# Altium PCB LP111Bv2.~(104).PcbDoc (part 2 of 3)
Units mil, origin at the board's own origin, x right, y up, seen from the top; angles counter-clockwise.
Board outline 3543.31 x 7480.32 mil, 4 copper layers (Top Layer, Signal Layer 1, Signal Layer 2, Bottom Layer), stack 40 mil thick; 284 components, 118 nets, 594 pads, 103 vias.
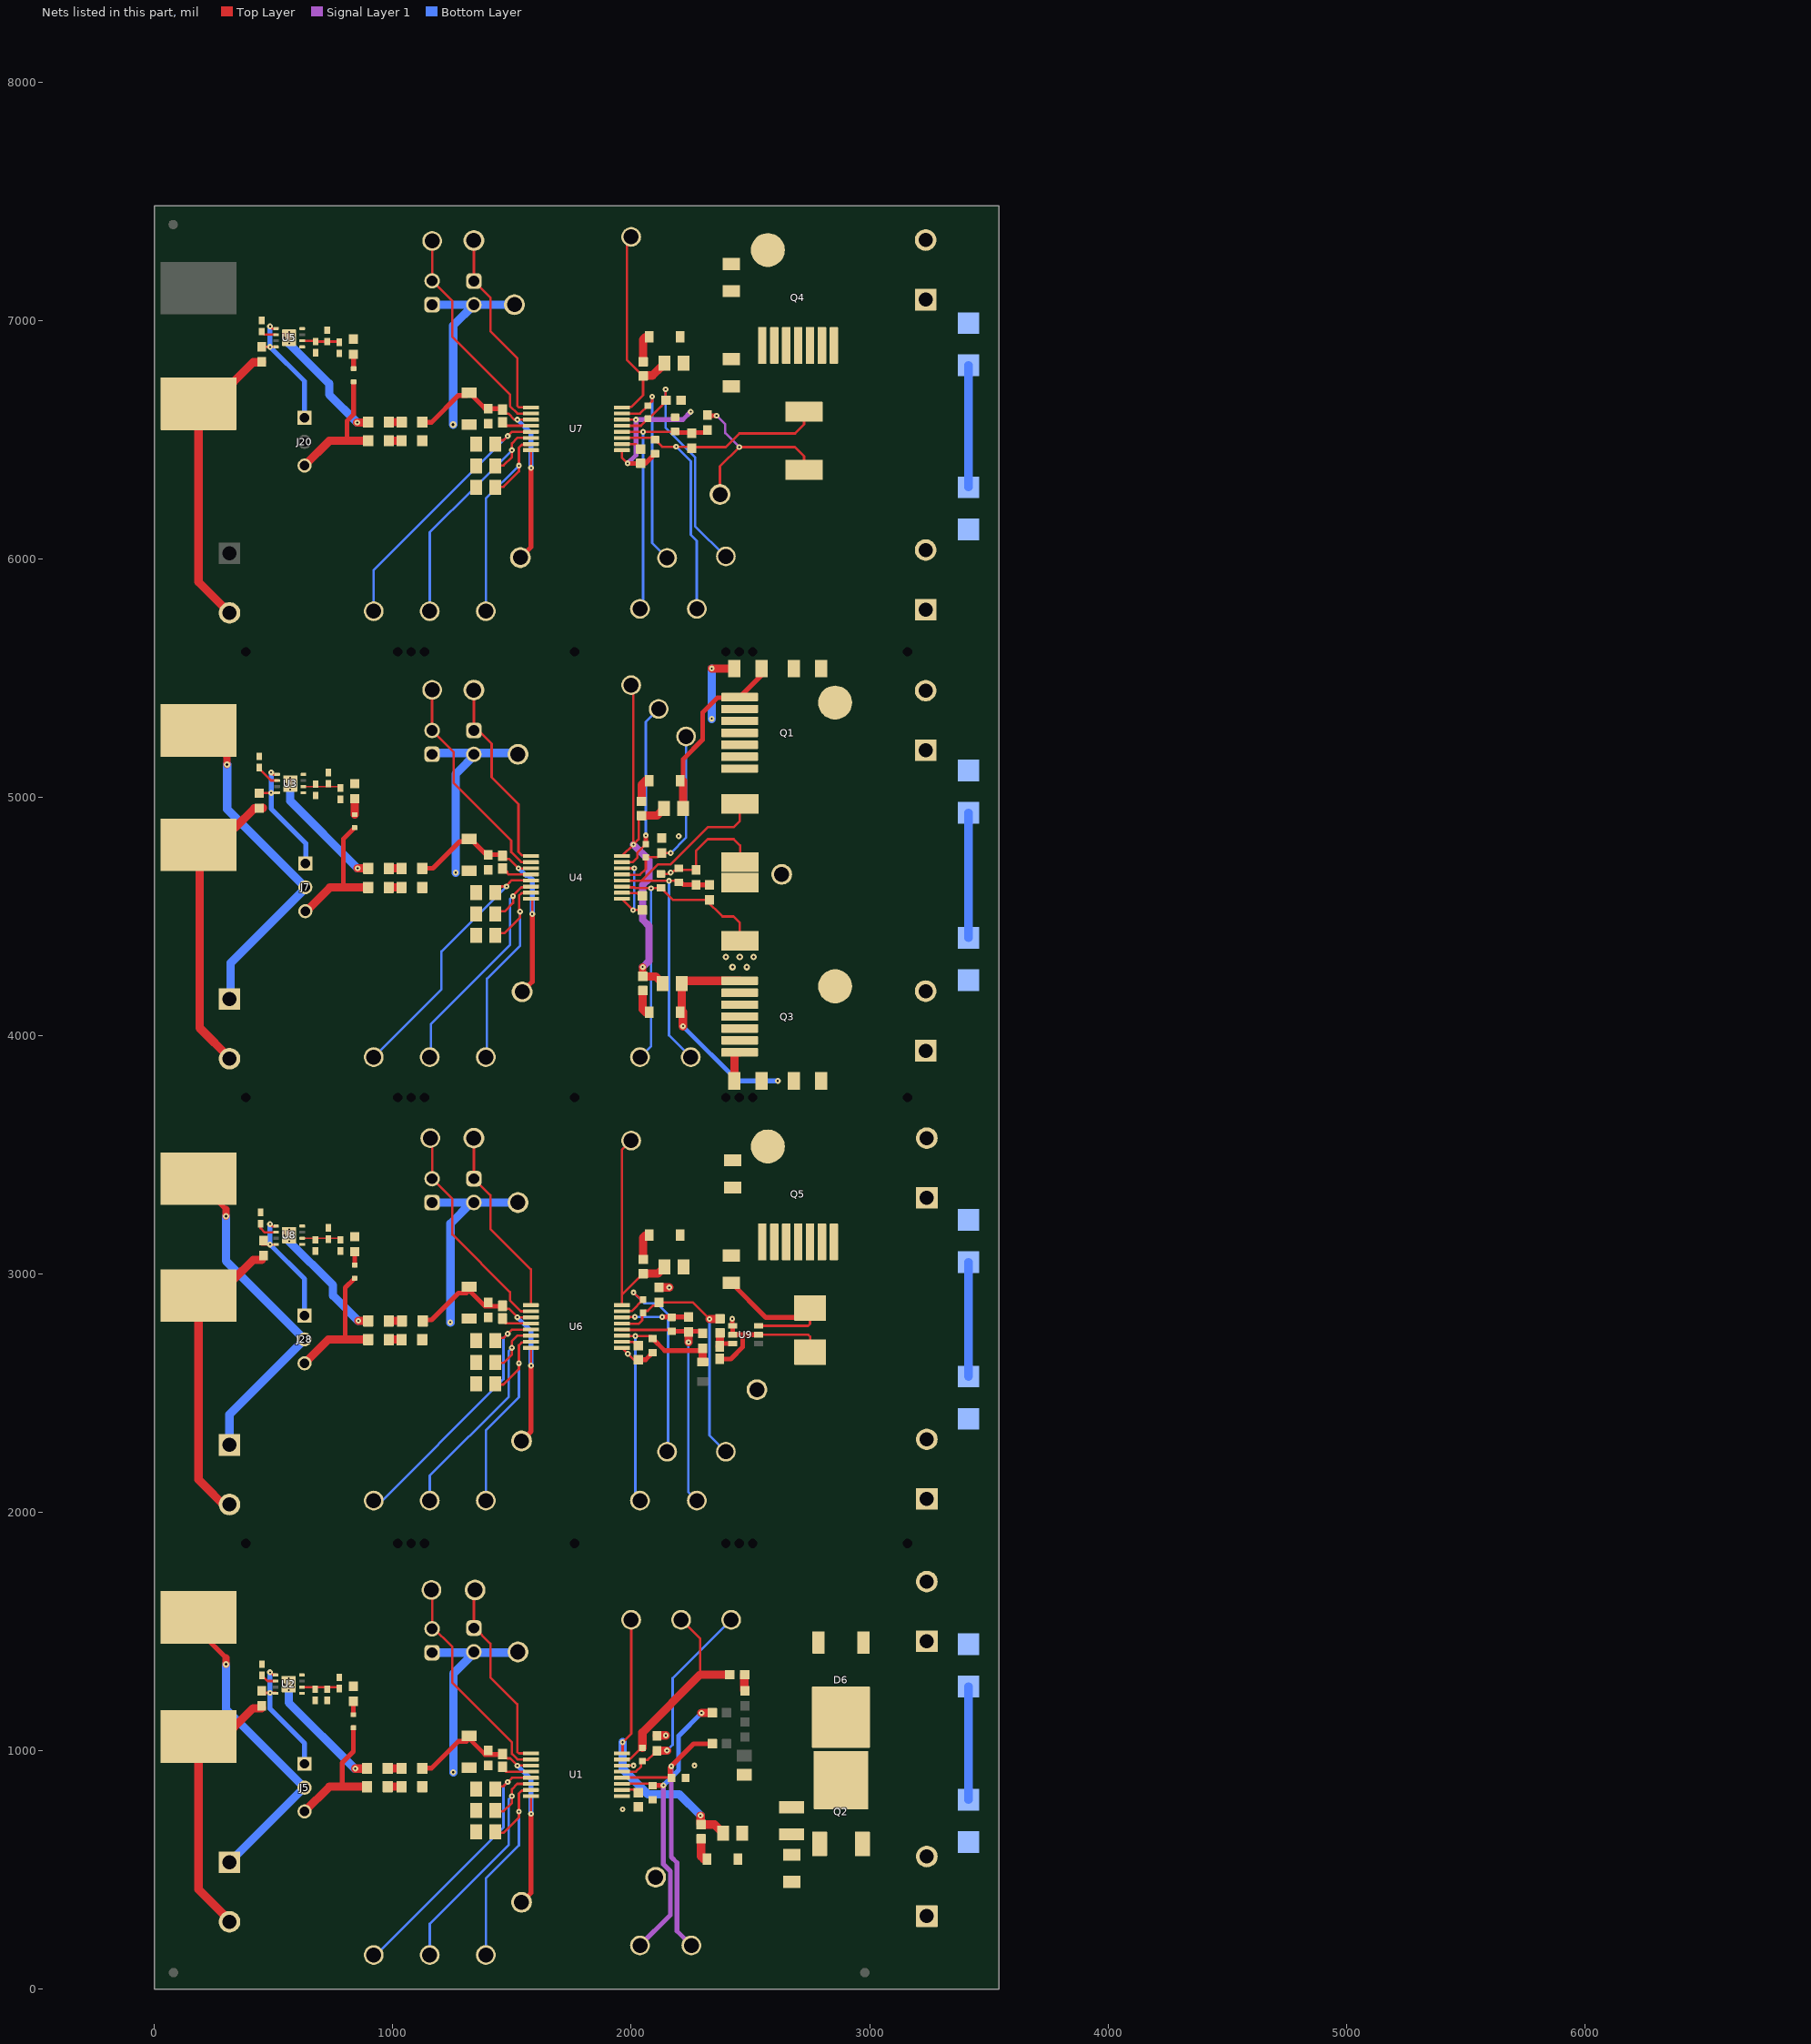
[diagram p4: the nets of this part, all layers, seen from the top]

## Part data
C1 C16 C33 C42: library part CMP-0081062-1, "CAP, CERM, 10 µF, 25 V,+/- 5%, X7R, AEC-Q200 Grade 1, 1206", Cap_Case=1206_180, Manufacturer=Kemet, Supplier Part Number 1=399-15734-1-ND, TempCo=X7R, Tolerance_%=5%, Value2=25V, ValueDisplayed=10µF
C2 C9 C19 C24 C34 C39 C43 C49: library part CMP-0007139-4, "CAP, CERM, 1 uF, 25 V, +/- 10%, X7R, AEC-Q200 Grade 1, 0603", Cap_Case=0603, Manufacturer=MuRata, Supplier Part Number 1=490-10673-1-ND, TempCo=X7R, Tolerance_%=10%, Value1=Unknown, Value2=25V, ValueDisplayed=1uF
C3 C5 C12 C15 C29 C31 C45 C52: library part CMP-0007501-1, "CAP, CERM, 10 uF, 25 V, +/- 20%, X5R, 0603", Cap_Case=0603, Manufacturer=MuRata, Supplier Part Number 1=490-12323-1-ND, TempCo=X5R, Tolerance_%=20%, Value1=Unknown, Value2=25V, ValueDisplayed=10uF
C4 C20 C35 C44 C53: library part CMP-0087061-2, "CAP CER 0.1UF 50V X7R 0603", Manufacturer=Kemet, TempCo=15%, Tolerance_%=10%
C6 C22 C37 C46: library part CMP-0030960-1, "Cap Ceramic 330nF 25V X7R 10% Pad SMD 0603 +125°C Automotive T/R", Manufacturer=TDK, Operating Temperature Range="-55°C to +125°C", TempCo=0.15, Temperature Characteristic=X7R, Tolerance_%=0.1%, ValueDisplayed=330nF
C7 C11 C13 C14 C30 C32 C47 C51: library part CMP-0006658-2, "CAP, CERM, 0.01 uF, 25 V, +/- 10%, X7R, 0402", Cap_Case=0402, Manufacturer=MuRata, Supplier Part Number 1=490-1312-1-ND, TempCo=X7R, Tolerance_%=10%, Value1=Unknown, Value2=25V, ValueDisplayed=0.01uF
C8 C10 C25 C26 C40 C41 C48 C50: library part CMP-0094870-1, "1000 pF ±10% 16V Ceramic Capacitor X7R 0603 (1608 Metric)", Digikey Part Number=311-4063-1-ND, Manufacturer=YAGEO, Mouser Part Number=603-CC603KRX7R7BB102, Operating Temperature Range="-55°C to +125°C", TempCo=15%, Temperature Characteristic=X7R, Tolerance_%=10%, ValueDisplayed="1.0 nF", Voltage=16V
C17: library part CMP-0009248-2, "CAP, CERM, 0.022 uF, 630 V, +/- 10%, X7R, 1210", Cap_Case=1210, Manufacturer=MuRata, Supplier Part Number 1=490-3514-1-ND, TempCo=X7R, Tolerance_%=10%, Value1=Unknown, Value2=630V, ValueDisplayed=0.022uF
C18 C23 C27 C38 C55: library part CMP-0008897-2, "CAP, CERM, 100 pF, 1000 V, +/- 5%, U2J, 1206", Cap_Case=1206, Manufacturer=MuRata, Supplier Part Number 1=490-4301-1-ND, TempCo=U2J, Tolerance_%=5%, Value1=Unknown, Value2=1000V, ValueDisplayed=100pF
C21 C28 C36 C54: library part CMP-0008902-2, "CAP, CERM, 68 pF, 1000 V, +/- 5%, U2J, 1206", Cap_Case=1206, Manufacturer=MuRata, Supplier Part Number 1=490-4300-1-ND, TempCo=U2J, Tolerance_%=5%, Value1=Unknown, Value2=1000V, ValueDisplayed=68pF
D1 D2 D3 D4 D11: library part CMP-0028526-2, "Diode, Schottky, 40 V, 0.5 A, SOD-123", Manufacturer="ON Semiconductor", Value1=0.5A, Value2=0.51V
D5 D8 D9 D12: library part CMP-0087203-1, "DIODE SCHOTTKY 60V 200MA SOD523", Manufacturer=Nexperia
D6: library part CMP-0092653-1, "Diode Silicon Carbide Schottky 600 V 11A (DC) Surface Mount TO-252-2", Digikey Part Number=C3D03060E-ND, Forward Current=11A, Manufacturer=Cree, Max Surge Forward Current=26A, Mouser Part Number=941-C3D03060E, Operating Temperature Range="-55°C to +175°C", Peak Reverse Current=4uA, ValueDisplayed=166pF
D7 D10 D13 D14 D17 D18: library part CMP-03913-133963852-1, "824520402 Tvs Diode, Unidir, 400V, Smb Rohs Compliant: Yes", Leakage Current=1µA, Max Operating Temperature=150°C, Min Operating Temperature=-65°C
D15 D16: library part CMP-03913-133963857-1, "824521402 Tvs Diode, Bidir, 400V, Do-214Aa Rohs Compliant: Yes", Leakage Current=1µA, Max Operating Temperature=150°C, Min Operating Temperature=-65°C
FB1 FB2 FB3 FB4 FB5 FB6 FB7 FB8 FB9 FB10 FB11 FB12 FB13 FB14 FB15 FB16: library part CMP-0124406-1, "2.5 kOhms @ 100 MHz 1 Signal Line Ferrite Bead 0805 (2012 Metric) 200mA 700mOhm", Digikey Part Number=553-BBBK00201209252Y00CT-ND, Impedance At Frequency="2500Ω @ 100MHz", Manufacturer="Pulse Electronics", Mouser Part Number=673-BBBK201209252Y00, Operating Temperature Range="-55°C to +125°C", Tolerance_%=25%
FID1 FID2 FID3: library part CMP-0077181-1, "Fiducial mark.  There is nothing to buy or mount.", Manufacturer=N/A
H1 H2 H3 H4 H5 H6 H7 H8 H9 H10 H11 H12 H13 H14 H15 H16: library part CMP-0003620-1, "Bumpon, Hemisphere, 0.44 X 0.20, Clear", Manufacturer=3M, Supplier Part Number 1=SJ5303-7-ND
J1 J4 J15 J19: library part CMP-0079575-1, "Banana Jack Insul Nylon Red, TH", Color=Red, Current_A=15A, Manufacturer="Cinch Connectivity", Supplier Part Number 1=J151-ND
J2 J10 J17 J21: library part CMP-0079574-1, "Banana Jack Insul Nylon Black, TH", Color=Black, Current_A=15A, Manufacturer="Cinch Connectivity", Supplier Part Number 1=J152-ND
J3 J9 J11 J12 J13 J18 J22 J23 J24 J27 J31 J32: library part CMP-0093233-2, Current_A=32A, Digikey Part Number=732-691250610002-ND, Manufacturer="Wurth Electronics", Mouser Part Number=710-691250610002, Operating Temperature Range="-32°C to +120°C", Voltage_V=450V
J5 J7 J20 J28: library part CMP-0002338-1, "Header, 100mil, 3x1, Tin, TH", Color=Black, Current_A=3A, Manufacturer="Sullins Connector Solutions", Supplier Part Number 1=S1012E-03-ND, Voltage_V=1.8kV
J6 J8 J14 J16 J25 J26 J29 J30: library part CMP-0054794-2, "Header, 2.54 mm, 2x1, Gold, TH", Color=Black, Manufacturer="Wurth Elektronik", Supplier Part Number 1=732-5315-ND
Logo1: library part CMP-0074844-1
Logo2: library part CMP-0074838-1, "Texas Instrument Corporate Signature"
Logo3: library part CMP-0074847-1, "FCC_disclaimer"
Logo4: library part CMP-0074769-1
LOGO5 LOGO6 LOGO7 LOGO8: library part CMP-0074835-1, "IEC 61010-1 High Voltage Warning"
LOGO9: library part CMP-0074837-2, "IEC 61010-1 Hot Surface Warning", Manufacturer="Texas Instruments"
LOGO10: library part CMP-0074836-1, "IEC 61010-1 Caution Warning"
Q1 Q3 Q4 Q5: library part CMP-0120465-1, "MOSFET N-Channel 750 V 44A (Tc) 197W (Tc) Surface Mount D2PAK-7", Digikey Part Number=2312-UJ4C075033B7SCT-ND, Drain To Source Breakdown Voltage=750V, Input Capacitace At Vds="1400pF @ 400V", Manufacturer=Qorvo, Mouser Part Number=431-UJ4C075033B7S, Operating Temperature Range="-55°C to +175°C", Power_W=197W, Pulse Drain Current=140A, Typ Forward Diode Voltage=1.26V
Q2: library part CMP-0000528-4, "Transistor, IGBT, 600 V, 20 A, DPAK", Manufacturer=STMicroelectronics, Value1="20 A"
R1 R2 R3 R22 R23 R24 R34 R35 R36 R38 R39 R40: library part CMP-0020622-3, "RES, 100 k, 5%, 0.125 W, AEC-Q200 Grade 0, 0805", Manufacturer=Panasonic, Power_W=125mW, Supplier Part Number 1=P100KACT-ND, TempCo="200 ppm/C", Tolerance_%=5%, Value2=0.125W, Value_Code=100k
R4 R7 R13 R14 R16 R17 R21 R27 R30 R37 R46 R51: library part CMP-0031931-1, "0 Ohms Jumper Chip Resistor 0603 (1608 Metric) Metal Element", Digikey Part Number=541-3927-1-ND, Manufacturer=Vishay, Mouser Part Number=71-WSL060300000ZEA9, Operating Temperature Range="-65°C to +170°C", TempCo=3900ppm/°C
R5 R6 R10 R31 R48: library part CMP-0020848-3, "RES, 10.2, 1%, 0.125 W, AEC-Q200 Grade 0, 0805", Manufacturer=Vishay-Dale, Power_W=125mW, Supplier Part Number 1=541-10.2CCT-ND, TempCo="100 ppm/C", Tolerance_%=1%, Value2=0.125W, Value_Code=10R2, ValueDisplayed=10.2
R8 R11 R32 R49: library part CMP-0026693-1, "RES, 294 k, 1%, 0.1 W, AEC-Q200 Grade 0, 0402", Manufacturer=Panasonic, Power_W=100mW, Supplier Part Number 1=P294KLCT-ND, TempCo="100 ppm/C", Tolerance_%=1%, Value2=0.1W, Value_Code=294k
R9 R12 R33 R50: library part CMP-0026711-1, "RES, 90.9 k, 1%, 0.1 W, AEC-Q200 Grade 0, 0402", Manufacturer=Panasonic, Power_W=100mW, Supplier Part Number 1=P90.9KLCT-ND, TempCo="100 ppm/C", Tolerance_%=1%, Value2=0.1W, Value_Code=90k9, ValueDisplayed=90.9k
R15: library part CMP-0022494-4, "RES, 54.9 k, 1%, 0.1 W, AEC-Q200 Grade 0, 0603", Manufacturer=Vishay-Dale, Power_W=100mW, Supplier Part Number 1=541-54.9KHCT-ND, TempCo="100 ppm/C", Tolerance_%=1%, Value2=0.1W, Value_Code=54k9, ValueDisplayed=54.9k
R18: library part CMP-0022205-4, "RES, 20.5 k, 1%, 0.1 W, AEC-Q200 Grade 0, 0603", Manufacturer=Vishay-Dale, Power_W=100mW, Supplier Part Number 1=541-20.5KHCT-ND, TempCo="100 ppm/C", Tolerance_%=1%, Value2=0.1W, Value_Code=20k5, ValueDisplayed=20.5k
R19: library part CMP-0080491-1, "RES, 3.40 k, 1%, 0.1 W, 0603", Manufacturer="TT Electronics/IRC", Power_W=100mW, TempCo="100 ppm/C", Tolerance_%=1%, Value2=0.1W, Value_Code=3k40, ValueDisplayed=3.40k
R20: library part CMP-0021540-3, "RES, 11.5 k, 1%, 0.125 W, AEC-Q200 Grade 0, 0805", Manufacturer=Panasonic, Power_W=125mW, Supplier Part Number 1=P11.5KCCT-ND, TempCo="100 ppm/C", Tolerance_%=1%, Value2=0.125W, Value_Code=11k5, ValueDisplayed=11.5k
R25 R29 R41 R42 R44 R45: library part CMP-0025909-5, "RES, 2.0 k, 5%, 0.1 W, 0603", Manufacturer=Yageo, Power_W=100mW, Supplier Part Number 1=311-2.0KGRCT-ND, TempCo="100 ppm/C", Tolerance_%=5%, Value2=0.1W, Value_Code=2k00, ValueDisplayed=2.0k
R26 R28 R43: library part CMP-0123876-1, "Res Metal Strip 2512 0.06 Ohm 1% 3W ±50ppm/°C Pad SMD Automotive T/R", Digikey Part Number=118-CRA2512-FZ-R060ELFCT-ND, Manufacturer=Bourns, Mouser Part Number=652-CRA2512FZR060ELF, Operating Temperature Range="-55°C to +170°C", Power_W=3W, TempCo=50ppm/°C, Tolerance_%=1%
R47: library part CMP-0092692-1, "RES SMD 0 OHM JUMPER 1/8W 0805", Digikey Part Number=311-0.0CRCT-ND, Manufacturer=Yageo, Mouser Part Number=603-RC0805FR-070RL, Operating Temperature Range="-55°C to +155°C", Power_W=125mW, Tolerance_%=1%
R52: library part CMP-0120455-1, "Res Metal Plate 2512 0.003 Ohm 1% 3W ±75ppm/C Pad SMD Automotive T/R", Digikey Part Number=P17091CT-ND, Manufacturer=Panasonic, Mouser Part Number=667-ERJ-MS4SF3M0U, Operating Temperature Range="-65°C to +170°C", Power_W=3W, TempCo=75ppm/°C, Tolerance_%=1%
SH-J1 SH-J2 SH-J3 SH-J4 SH-J5 SH-J6 SH-J7 SH-J8 SH-J9 SH-J10 SH-J11 SH-J12: library part CMP-0003623-3, "Shunt, 100mil, Gold plated, Black", Alternate Manufacturer=3M, Alternate PartNumber=969102-0000-DA, Manufacturer=Samtec, Supplier Part Number 1=SAM8858-ND
TP1 TP3 TP4 TP7 TP9 TP10 TP11 TP12 TP13 TP15 TP16 TP17 TP18 TP20 TP21 TP22 TP23 TP24 TP27 TP29 TP31 TP32 TP33 TP34 TP35 TP36 TP37 TP38 TP42 TP43 TP46 TP47 TP48 TP49 TP50 TP51: library part CMP-1672-00004-4, "Test Point, White, Through Hole, RoHS, Bulk", Colour=White, Manufacturer=Keystone, Package Quantity=100
TP2 TP8 TP28 TP41: library part CMP-0055151-2, "Test Point, Multipurpose, Yellow, TH", Color=Yellow, Manufacturer="Keystone Electronics", PartNumber=5014, Supplier Part Number 1=36-5014-ND
TP5 TP14 TP30 TP44: library part CMP-0055147-2, "Test Point, Multipurpose, Red, TH", Color=Red, Manufacturer="Keystone Electronics", PartNumber=5010, Supplier Part Number 1=36-5010-ND
TP6 TP19 TP25 TP26 TP39 TP40 TP45 TP52: library part CMP-0055148-2, "Test Point, Multipurpose, Black, TH", Color=Black, Manufacturer="Keystone Electronics", Supplier Part Number 1=36-5011-ND
U1: library part CMP-0123884-1, Manufacturer="Texas Instruments", Operating Temperature Range=to
U2 U3 U5 U8: library part CMP-0073868-3, "Vin 3V to 36V, 150mA, Ultra-Low-Noise, High-PSRR Low-Dropout (LDO) Linear Regulator, DRB0008A (VSON-8)", Alternate Manufacturer="Texas Instruments", Alternate PartNumber=TPS7A4901DRBT, Operating Temperature Range="-40 to 125 C", Rating=Catalog
U4: library part CMP-0001684-2, "Automotive Reinforced Isolated Switch Driver with Integrated 15-V Gate Supply and Fault Indicators", Manufacturer="Texas Instruments", Max Power Dissipation=250mW, Max Supply Voltage=5.5V, Min Supply Voltage=4.5V, Operating Temperature Range="-40°C to +150°C"
U6 U7: library part CMP-0029491-2, "Automotive Reinforced Isolated Switch Driver with Integrated 15-V Gate Supply and Fault/Alarm Indicators", Manufacturer="Texas Instruments", Max Supply Voltage=5.5V, Min Supply Voltage=4.5V, Operating Temperature Range="-40°C to +150°C"
U9: library part CMP-0013230-2, "Bidirectional, Low- and High-Side Measurement, Multichannel, Voltage Output, Current-Sense Amplifier, DBV0006A (SOT-6)", Alternate Manufacturer="Texas Instruments", Alternate PartNumber=INA181A1IDBVT
ZZ1: library part CMP-0003616-3
ZZ2: library part CMP-0077236-1
ZZ3: library part CMP-0077237-1
ZZ4: library part CMP-0077238-1

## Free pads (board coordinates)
  round 0 hole 39.37 slot 1181.1 at 0 deg unplated mask+1: 0(383.67,1870.08) 0(383.67,3740.16) 0(383.67,5610.24) 0(1762.77,1870.08) 0(1762.77,3740.16) 0(1762.77,5610.24)
  round 0 hole 39.37 unplated mask+1: 0(1020.45,1870.08) 0(1020.45,3740.16) 0(1020.45,5610.24) 0(1076.77,1870.08) 0(1076.77,3740.16) 0(1076.77,5610.24) 0(1133.09,1870.08) 0(1133.09,3740.16) 0(1133.09,5610.24) 0(2397.02,1870.08) 0(2397.02,3740.16) 0(2397.02,5610.24) 0(2453.33,1870.08) 0(2453.33,3740.16) 0(2453.33,5610.24) 0(2509.65,1870.08) 0(2509.65,3740.16) 0(2509.65,5610.24)
  round 0 hole 39.37 slot 1200.79 at 0 deg unplated mask+1: 0(3159.26,1870.08) 0(3159.26,3740.16) 0(3159.26,5610.24)

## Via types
v1: diameter 24, hole 8, Top Layer to Bottom Layer, tented both sides, 77 vias
v2: diameter 19.68, hole 7.87, Top Layer to Bottom Layer, 16 vias
v3: diameter 27.56, hole 11.81, Top Layer to Bottom Layer, tented both sides, 10 vias

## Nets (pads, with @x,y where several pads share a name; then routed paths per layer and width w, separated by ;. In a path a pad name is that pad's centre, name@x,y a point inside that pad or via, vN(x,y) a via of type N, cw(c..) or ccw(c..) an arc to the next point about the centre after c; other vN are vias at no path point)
1ALM1_CMP: C38.1 C40.2 Q4.2 Q4.3 Q4.4 Q4.5 Q4.6 Q4.7 R41.2 R43.2 TP35.1 U7.11 | length 1597.3
  Top Layer w10: U7.11@1960.95,6506.89 2092.64,6506.89 C40.2@2100,6499.53 2129.53,6470 v1(2188.52,6470) 2247.51,6470 R41.2@2254,6463.5 2258.97,6468.47 2396.54,6468.47 2453.98,6525.91 2687.25,6525.91 2725.28,6563.94 R43.2@2725.28,6621.46
  Bottom Layer w10: v1(2188.52,6470) 2250,6408.52 2250,6100.09 2275,6075.09 TP35.1@2275,5790
1CE: J26.2 TP33.1 U7.2 | length 928
  Top Layer w10: TP33.1@1165,7333.03 J26.2@1165,7165.82 1250,7080.82 1250,6930.97 1491.74,6689.24 1491.74,6640.71 1523.2,6609.25 U7.2@1579.06,6609.25
1EN: J25.1 TP28.1 U7.1 | length 828.6
  Top Layer w10: TP28.1@1340,7335 J25.1@1340,7165 1409.46,7095.54 1409.46,6954.35 1522.17,6841.64 1522.17,6641.53 1528.86,6634.84 U7.1@1579.06,6634.84
1FLT1_CMP: C41.2 R41.1 R44.2 TP34.1 U7.12 | length 1099.1
  Top Layer w10: U7.12@1960.95,6532.48 v1(2050.01,6532.48) 2177.05,6532.48 C41.2@2180,6529.53
  Top Layer w20: C41.2@2180,6529.53 2308.03,6529.53 R44.2@2310,6531.5
  Bottom Layer w10: TP34.1@2036.59,5790 2050.01,5803.42 v1(2050.01,6532.48)
1HV+: C36.1 D17.1 J23.1 J23.2 Q4.8
1LDO_IN+: C29.1 J20.1 U5.5 U5.8 | length 532.8
  Top Layer w10: C29.1@449.96,6889.48 450.62,6888.82 v1(485,6888.82) U5.8@509.76,6888.82 ; v1(485,6975) 494.41,6965.59 U5.5@509.76,6965.59
  Bottom Layer w20: v1(485,6975) v1(485,6888.82) 629.87,6743.95 J20.1@629.87,6590.99
1LDO_OUT: C30.1 C31.1 D9.2 R32.2 U5.1 | length 60.6
  Top Layer w20: C31.1@835,6857.98 835.46,6857.52 D9.2@835.46,6797.56
1nALM1: R40.2 TP38.1 U7.7 | length 956.5
  Top Layer w10: R40.2@1430,6300 1431.78,6301.78 1464.14,6301.78 1528.86,6366.49 v1(1528.86,6390.99) 1528.86,6466.41 1540.67,6478.23 1581.29,6478.23 U7.7@1584.36,6481.3
  Bottom Layer w10: TP38.1@1390,5780 1390,6252.14 v1(1528.86,6390.99)
1nFLT1: R39.2 TP37.1 U7.6 | length 1054.6
  Top Layer w10: R39.2@1430,6390 1431.92,6391.92 1464.14,6391.92 1499.54,6427.32 v1(1499.54,6455.79) 1499.54,6484.26 1522.17,6506.89 U7.6@1584.36,6506.89
  Bottom Layer w10: TP37.1@1155,5780 1155,6111.25 1339.48,6295.73 v1(1499.54,6455.79)
1PGOOD: R38.2 TP36.1 U7.5 | length 1143.6
  Top Layer w10: R38.2@1430,6480 1447.09,6497.09 1464.14,6497.09 v1(1481.84,6514.78) 1499.54,6532.48 U7.5@1584.36,6532.48
  Bottom Layer w10: TP36.1@920,5780 920,5952.94 v1(1481.84,6514.78)
1RESP: R21.1 U7.10 | length 88
  Top Layer w10: U7.10@1960.95,6481.3 2018.42,6481.3 R21.1@2040,6459.72
1VDDH: C37.1 TP31.1 U7.15 | length 871.2
  Top Layer w10: U7.15@1960.95,6609.25 2036.69,6609.25 C37.1@2070,6642.56 2087.93,6660.49 v1(2087.93,6680.43)
  Bottom Layer w10: v1(2087.93,6680.43) 2087.93,6066.22 TP31.1@2150.72,6003.43
1VDDM: C37.2 C39.2 TP32.1 U7.13 | length 1068.9
  Top Layer w10: U7.13@1960.95,6558.07 2040.62,6558.07 2078.78,6596.23 2082.21,6596.23 2125.31,6639.33 2126.3,6639.33 2140,6653.03 C39.2@2140,6654.02 ; v1(2144.08,6710.42) 2144.08,6666.91 C39.2@2145.55,6665.43
  Bottom Layer w10: v1(2144.08,6710.42) 2144.08,6549.61 2267.87,6425.82 2267.87,6136.84 TP32.1@2394.53,6010.18
1VDDP: D9.1 FB5.1 J20.3 | length 572.2
  Top Layer w20: 815.29,6495 807.43,6502.85 807.43,6578.09 835.46,6606.12 D9.1@835.46,6742.44
  Top Layer w35: J20.3@629.87,6390.99 733.88,6495 815.29,6495 FB5.1@896.69,6495
1VDDP_filtered: C33.1 C34.1 C35.2 FB13.2 J25.2 J26.1 R38.1 R39.1 R40.1 TP30.1 U7.4 | length 1008
  Top Layer w10: C35.2@1460,6572.65 1474.58,6558.07 U7.4@1579.06,6558.07
  Bottom Layer w35: J26.1@1165,7065.82 TP30.1@1510,7065.82 ; v3(1253.12,6563.07) 1253.12,6978.12 J25.2@1340,7065
1VDRV: R6.1 R17.1 TP29.1 U7.16 | length 926.3
  Top Layer w10: U7.16@1960.95,6634.84 1962.75,6636.65 2000.75,6636.65 2050.01,6685.91 R17.1@2050.01,6766.26 1981.5,6834.77 1981.5,7311.84 2000,7330.33 TP29.1@2000,7350
  Top Layer w35: R17.1@2050.01,6766.26 2052.39,6768.64 2088.93,6768.64 2126,6805.71 2132.5,6805.71 2140,6813.21 R6.1@2140,6819.71
1VGATE: C36.2 C38.2 D4.2 Q4.1 R6.2
1VSSP: C29.2 C31.2 C32.2 FB6.1 J21.1 J22.2 R33.1 U5.4 U5.9 | length 1765.4
  Top Layer w35: J22.2@314.96,5773.19 185,5903.15 J21.1@185,6650 277.5,6742.5 332.5,6742.5 414.3,6824.3 448.76,6824.3 449.96,6825.5 C29.2@449.96,6826.48 ; v1(850.87,6571.51) 894.99,6571.51 FB6.1@896.69,6573.22
  Bottom Layer w35: v2(564.88,6902.6) 733.15,6734.33 733.15,6689.24 v1(850.87,6571.51)
  other v2: 545.2,6927.2 584.57,6927.2 564.88,6951.81
1VSSP_filtered: C33.2 C34.2 C35.1 FB14.2 TP39.1 U7.3 U7.8 | length 1255
  Top Layer w10: C35.1@1460,6625.85 1460,6623.09 1473.86,6609.23 1484.51,6609.23 1510.07,6583.66 v1(1522.48,6583.66) U7.3@1579.06,6583.66 ; U7.8@1579.06,6455.71 1580,6454.76 v1(1580,6381.24)
  Top Layer w20: FB14.2@1120.08,6572.65 1163.14,6572.65 1275.92,6685.43 1308.5,6685.43 C33.2@1320,6696.93 1386.94,6629.99 C34.2@1400,6629.99 1455.86,6629.99 C35.1@1460,6625.85 ; TP39.1@1535,6005 1580,6050 v1(1580,6381.24)
  Bottom Layer w20: v1(1522.48,6583.66) 1580,6526.14 v1(1580,6381.24)
1VSSS: C39.1 C40.1 C41.1 D18.2 J27.1 J27.2 R21.2 R43.1 R44.1 TP40.1 U7.9 U7.14 | length 1454.7
  Top Layer w10: U7.9@1960.95,6455.71 1960.95,6424.58 v1(1985.25,6400.28) ; U7.14@1960.95,6583.66 v1(2020.04,6583.66) ; TP40.1@2372.36,6299.38 2372.36,6387.53 v1(2453.33,6468.5) 2686.97,6468.5 2725,6430.47 R43.1@2725,6372.95
  Top Layer w20: v1(1985.25,6400.28) R21.2@2040,6400.28 2059.8,6400.28 C40.1@2100,6440.47 ; R44.1@2320,6602.44 2322.13,6600.31 v1(2358.03,6600.31)
  Signal Layer 1 w10: v1(2358.03,6600.31) 2394.53,6563.81 2394.53,6527.31 v1(2453.33,6468.5)
  Signal Layer 1 w20: v1(1985.25,6400.28) 2020.04,6435.07 v1(2020.04,6583.66) 2216.52,6583.66 v1(2249.53,6616.67)
2CE: J16.2 TP18.1 U4.2 | length 940
  Top Layer w10: TP18.1@1164.81,5449.81 J16.2@1164.81,5280 1254.94,5189.87 1254.94,5060.03 1496.67,4818.29 1496.67,4769.77 1538.19,4728.25 1600.95,4728.25 U4.2@1601.71,4727.49
2EN: J14.1 TP8.1 U4.1 | length 843.2
  Top Layer w10: J14.1@1340,5280 TP8.1@1340,5449.51 ; J14.1@1344.93,5294.05 1414.4,5224.59 1414.4,5083.4 1527.1,4970.7 1527.1,4770.59 1541.54,4756.15 1591.52,4756.15 U4.1@1594.59,4753.08
2FLT1_CMP: C23.1 C26.2 Q1.2 Q1.3 Q1.4 Q1.5 Q1.6 Q1.7 R25.1 R28.2 R29.2 TP20.1 U4.12 | length 2011.2
  Top Layer w10: U4.12@1968.1,4649.11 2042.67,4649.11 ; C26.2@2187.16,4646.16 2184.2,4649.11 v1(2158.46,4649.11) 2042.67,4649.11 ; R28.2@2455.78,4972.05 2455.78,4900.68 2429.38,4874.28 2321.27,4874.28 2165.35,4718.37 2111.92,4718.37 2042.67,4649.11
  Top Layer w20: C26.2@2199.2,4642.69 2204.95,4636.94 2214.7,4636.94 2218.64,4633 2263.03,4633 2264.15,4631.89 R29.2@2271.73,4631.89 ; R29.2@2271.81,4631.97 R25.1@2313.5,4631.97
  Top Layer w35: v1(2337.53,5540) C23.1@2432.91,5540
  Bottom Layer w10: v1(2158.46,4649.11) 2158.46,4001.54 TP20.1@2250,3910
  Bottom Layer w35: v1(2337.53,5328.91) v1(2337.53,5540)
2FLT2_CMP: C25.2 C27.1 Q3.2 Q3.3 Q3.4 Q3.5 Q3.6 Q3.7 R25.2 R26.2 TP21.1 U4.11 | length 1499.5
  Top Layer w10: U4.11@1960.95,4625.13 1964.02,4622.06 2012.98,4622.06 2015.52,4619.53 2126.97,4619.53 2137.72,4608.78 2137.72,4606.81 2175.55,4568.98 2313.5,4568.98 2382.9,4499.57 2429.43,4499.57 2455.82,4473.18 R26.2@2455.82,4401.81
  Top Layer w35: C27.1@2432.91,3810 2432.91,3929.78 2433.13,3930 Q3.7@2455,3930
  Bottom Layer w10: TP21.1@2036.59,3910 2083.25,3956.67 v1(2083.25,4617.88)
  other v3: 2425,4287.33 2485,4287.33 2397.02,4329.77 2455.17,4329.77 2513.56,4329.77
2HV+: C21.1 D15.2 J12.1 J12.2 Q1.8
2HV-: C28.1 D16.1 J18.1 J18.2 Q3.8
2LDO_IN+: C3.1 J7.1 U3.5 U3.8 | length 532.8
  Top Layer w10: C3.1@454.89,5018.53 455.55,5017.87 v1(489.94,5017.87) U3.8@514.7,5017.87 ; v1(489.94,5104.06) 499.35,5094.65 U3.5@514.7,5094.65
  Bottom Layer w20: v1(489.94,5104.06) 489.94,4951.62 634.81,4806.75 J7.1@634.81,4720.05
2LDO_OUT: C11.1 C12.1 D8.2 R8.2 U3.1 | length 67.3
  Top Layer w20: C12.1@840,4993.5 C12.1@840.94,4992.56
  Top Layer w35: D8.2@840,4927.56 C12.1@840,4993.5
2nFLT1: R23.2 TP23.1 U4.6 | length 1030.1
  Top Layer w10: R23.2@1434.94,4519.06 1436.86,4520.98 1469.08,4520.98 1504.47,4556.37 v1@1504.47,4587.43 ; R23.2@1441.88,4507.59 R23.2@1443.8,4509.52 ; v1(1504.47,4584.84) v1@1504.47,4587.43 ; U4.6@1579.06,4625.13 1575.98,4622.06 1539.1,4622.06 v1@1504.47,4587.43
  Bottom Layer w10: TP23.1@1159.94,3909.06 1159.94,4049.06 1491.11,4380.23 1491.11,4571.48 v1(1504.47,4584.84)
2nFLT2: R24.2 TP24.1 U4.7 | length 945.6
  Top Layer w10: R24.2@1434.94,4429.06 1436.71,4430.83 1469.08,4430.83 1533.79,4495.55 v1(1533.79,4520.05) 1531.11,4522.73 1531.11,4531.14 1529.34,4532.91 1529.34,4587.02 1539.65,4597.33 1576.85,4597.33 U4.7@1579.06,4599.54 ; R24.2@1441.88,4417.59 R24.2@1443.65,4419.37
  Bottom Layer w10: TP24.1@1394.94,3909.06 1394.94,4239.06 1533.79,4377.91 v1(1533.79,4520.05)
2PGOOD: R22.2 TP22.1 U4.5 | length 1135.8
  Top Layer w10: R22.2@1434.94,4609.06 1434.94,4610.78 1450,4625.85 v1(1476.98,4625.85) 1476.98,4629.64 1490.37,4643.03 1490.37,4643.65 1497.45,4650.72 U4.5@1604.48,4650.72
  Bottom Layer w10: TP22.1@924.94,3909.06 924.94,3914.94 1204.1,4194.1 1204.1,4352.97 v1(1476.98,4625.85)
2RESP: R27.1 U4.10 | length 88
  Top Layer w10: U4.10@1968.1,4597.93 2025.58,4597.93 R27.1@2047.16,4576.35
2VDDH: C22.1 TP15.1 U4.15 | length 710.8
  Top Layer w10: U4.15@1983.88,4725.88 1985.1,4727.1 2002.96,4727.1 2003.31,4727.46 2006.65,4727.46 2026.47,4747.28 2026.47,4768.48 C22.1@2061.28,4803.28
  Top Layer w20: C22.1@2061.28,4803.28 v1(2061.28,4840)
  Bottom Layer w10: v1(2061.28,4840) 2061.28,5316.28 TP15.1@2115,5370
2VDDM: C22.2 C24.2 TP16.1 U4.13 | length 780.5
  Top Layer w10: U4.13@1968.1,4674.7 2036.91,4674.7 2061.28,4699.07 C22.2@2061.28,4748.16 2111.01,4748.16 2127.72,4764.86 C24.2@2127.72,4765.85 v1(2165.74,4765.85)
  Bottom Layer w10: v1(2165.74,4765.85) 2230,4830.11 TP16.1@2230,5255
2VDDP: D8.1 FB3.1 J7.3 | length 574.5
  Top Layer w20: 792.5,4621.56 792.5,4824.94 D8.1@840,4872.44
  Top Layer w35: J7.3@634.81,4520.05 736.32,4621.56 792.5,4621.56 FB3.1@896.69,4621.56
2VDDP_filtered: C16.1 C19.1 C20.2 FB11.2 J14.2 J16.1 R22.1 R23.1 R24.1 TP14.1 U4.4 | length 1032.7
  Top Layer w10: C20.2@1460,4700.6 1484.29,4676.31 U4.4@1579.06,4676.31 ; C20.2@1464.94,4701.71 1479.52,4687.13
  Bottom Layer w35: J16.1@1176.17,5185.66 TP14.1@1521.17,5185.66 ; v1@1264.29,4682.91 1264.29,5097.96 J14.2@1351.17,5184.84
  other v1: 1263.52,4683.87
2VDRV: R5.1 R16.1 R30.1 R31.1 TP10.1 U4.16 | length 1691.1
  Top Layer w10: U4.16@1960.95,4753.08 v1(2009.2,4801.34) ; TP10.1@2000,5470 2009.2,5460.8 2009.04,5460.8 2009.04,4801.5 v1(2009.2,4801.34) ; R30.1@2043.84,4922.99 2031.02,4910.17 2031.02,4823.16 v1(2009.2,4801.34)
  Top Layer w30: R16.1@2048.5,4248.46 v1(2048.5,4287.33)
  Top Layer w35: R30.1@2043.84,4922.99 2107.68,4922.99 R31.1@2137.4,4952.71 ; R16.1@2048.5,4248.46 2102.56,4248.46 R5.1@2132.28,4218.74
  Signal Layer 1 w30: v1(2009.2,4801.34) 2074.41,4736.12 2074.41,4658.36 2048.38,4632.33 2048.38,4485.8 2074.41,4459.77 2074.41,4313.24 v1(2048.5,4287.33)
2VGATE1: C27.2 C28.2 D2.2 Q3.1 R5.2 | length 922
  Top Layer w35: v1(2216.92,4039.26) 2216.92,4099.6 2212.28,4104.23 R5.2@2212.28,4218.74 2223.54,4230 Q3.1@2455,4230
  Bottom Layer w20: v1(2216.92,4039.26) 2446.18,3810 v1(2615.19,3810)
2VGATE2: C21.2 C23.2 D3.2 Q1.1 R31.2 | length 776.5
  Top Layer w20: D3.2@2217.4,5068.2 2217.4,5158.66 2299.96,5241.22 2299.96,5355.07 2361.96,5417.07 2451.87,5417.07 2547.09,5512.28 C23.2@2547.09,5540
  Top Layer w35: R31.2@2217.4,4952.71 D3.2@2217.4,5068.2
2VSSP: C3.2 C12.2 C13.2 FB4.1 J10.1 J11.2 R9.1 U3.4 U3.9 | length 1763.9
  Top Layer w35: J11.2@319.9,3902.25 189.94,4032.21 189.94,4779.06 282.44,4871.56 337.44,4871.56 419.23,4953.35 453.69,4953.35 454.89,4954.55 C3.2@454.89,4955.54 ; v1(852.58,4701.56) FB4.1@896.69,4701.56 FB4.1@898.4,4703.26
  Bottom Layer w35: v2(569.88,5032.6) 569.88,4984.26 v1(852.58,4701.56)
  other v2: 550.2,5057.2 589.57,5057.2 569.88,5081.81
2VSSP_filtered: C16.2 C19.2 C20.1 FB12.2 TP26.1 U4.3 U4.8 | length 1186.4
  Top Layer w10: C20.1@1464.94,4754.91 1464.94,4745.57 1469.7,4740.8 1488,4740.8 v1(1527.1,4701.71) 1578.86,4701.71 U4.3@1579.06,4701.9 ; v1(1584.94,4510.29) U4.8@1584.94,4568.07
  Top Layer w20: FB12.2@1125.01,4701.71 1168.07,4701.71 1280.86,4814.49 1313.44,4814.49 1324.94,4825.99 1391.87,4759.05 1460.8,4759.05 C20.1@1464.94,4754.91 ; TP26.1@1542.55,4183.74 1584.94,4226.13 v1(1584.94,4510.29)
  Bottom Layer w20: v1(1527.1,4701.71) 1528.19,4701.71 1557.23,4672.66 1567.48,4672.66 1584.94,4655.2 v1(1584.94,4510.29)
2VSSS: C24.1 C25.1 C26.1 R26.1 R27.2 R28.1 R29.1 TP25.1 U4.9 U4.14 | length 861.6
  Top Layer w10: U4.9@1960.95,4573.95 v1(2008.08,4526.81) R27.2@2046.54,4526.81 ; U4.14@1960.95,4701.9 v1(2012.98,4701.9) ; C25.1@2125,4678.58 2165.74,4678.58 2165.74,4680.08 2172.21,4686.55 2173.7,4686.55 2178.15,4691 2188.46,4691 C26.1@2199.2,4701.75 2206.07,4694.88 R29.1@2271.73,4694.88 2271.73,4774.31 2321.27,4823.85 2430.34,4823.85 2456.74,4797.45 R28.1@2456.74,4726.08
  Bottom Layer w10: v1(2008.08,4526.81) 2012.98,4531.71 v1(2012.98,4701.9)
  other v1: 2165.74,4683.87 2199.2,4836.44
3ALM1_CMP: C50.2 R42.2 R47.1 TP51.1 U6.11 | length 1137.5
  Top Layer w10: U6.11@1951.57,2740 v1(2017.41,2740) 2083.26,2740 C50.2@2090.62,2732.64
  Top Layer w20: C50.2@2090,2729.53 2140.49,2679.04 2299.93,2679.04 R42.2@2299.93,2688.5
  Top Layer w35: R47.1@2299.93,2631.34 R42.2@2299.93,2688.5
  Bottom Layer w10: v1(2017.41,2740) 2017.41,2069.17 TP51.1@2036.59,2050
3CE: J30.2 TP27.1 U6.2 | length 919.6
  Top Layer w10: TP27.1@1165,3567.75 1165,3400.55 1250,3315.55 1250,3165.7 1491.74,2923.96 1491.74,2889.76 1537.48,2844.02 1579.02,2844.02 U6.2@1579.06,2843.98
3EN: J29.1 TP41.1 U6.1 | length 799.2
  Top Layer w10: TP41.1@1340,3569.73 1340,3399.72 1409.46,3330.26 1409.46,3189.07 1579.06,3019.48 U6.1@1579.06,2869.57
3FLT1_CMP: C48.2 R42.1 R45.2 TP48.1 U6.12 | length 1075.5
  Top Layer w10: U6.12@1951.57,2765.59 2167.67,2765.59 C48.2@2170.62,2762.64
  Top Layer w20: C48.2@2170,2759.53 2291.9,2759.53 R42.1@2299.93,2751.5
  Top Layer w35: v1(2240.07,2714.41) R45.2@2240.07,2757.48
  Bottom Layer w10: v1(2240.07,2714.41) 2240.07,2084.93 TP48.1@2275,2050
3HV+: C54.1 D13.1 J31.1 J31.2 Q5.8
3IN+: C55.1 Q5.2 Q5.3 Q5.4 Q5.5 Q5.6 Q5.7 R52.2 U9.3 | length 685.5
  Top Layer w10: U9.3@2536.02,2782.8 2741.77,2782.8 2750,2791.02 R52.2@2750,2852.52
  Top Layer w20: C55.1@2420,2962.91 2565.2,2817.72 2710.2,2817.72 R52.2@2750,2857.52
3LDO_IN+: C45.1 J28.1 U8.5 U8.8 | length 532.8
  Top Layer w10: C45.1@449.96,3124.2 450.62,3123.54 v1(485,3123.54) U8.8@509.76,3123.54 ; v1(485,3209.73) 494.41,3200.32 U8.5@509.76,3200.32
  Bottom Layer w20: v1(485,3209.73) v1(485,3123.54) 629.87,2978.67 J28.1@629.87,2825.72
3LDO_OUT: C51.1 C52.1 D12.2 R49.2 U8.1 | length 55.9
  Top Layer w20: D12.2@840,3037.56 C52.1@840,3093.5
3nALM1: R36.2 TP43.1 U6.7 | length 956.5
  Top Layer w10: R36.2@1430,2534.73 1431.78,2536.5 1464.14,2536.5 1528.86,2601.22 v1(1528.86,2625.72) 1528.86,2701.14 1540.67,2712.95 1581.29,2712.95 U6.7@1584.36,2716.03
  Bottom Layer w10: TP43.1@1390,2014.73 1390,2344.73 1528.86,2483.58 v1(1528.86,2625.72)
3nFLT1: R35.2 TP46.1 U6.6 | length 1054.6
  Top Layer w10: R35.2@1430,2624.73 1431.92,2626.65 1464.14,2626.65 1499.54,2662.04 v1(1499.54,2690.51) 1499.54,2718.98 1522.17,2741.62 U6.6@1584.36,2741.62
  Bottom Layer w10: TP46.1@1155,2014.73 1155,2154.73 1486.17,2485.9 1486.17,2677.15 v1(1499.54,2690.51)
3PGOOD: R34.2 TP42.1 U6.5 | length 1143.6
  Top Layer w10: R34.2@1430,2714.73 1447.09,2731.81 1464.14,2731.81 v1(1481.84,2749.51) 1499.54,2767.21 U6.5@1584.36,2767.21
  Bottom Layer w10: TP42.1@920,2014.73 1464,2558.73 1464,2731.67 v1(1481.84,2749.51)
3RESP: R37.1 U6.10 | length 88
  Top Layer w10: U6.10@1951.57,2714.41 2009.05,2714.41 R37.1@2030.62,2692.84
3VDDH: C46.1 TP47.1 U6.15 | length 932
  Top Layer w10: U6.15@1951.57,2842.37 1953.78,2844.58 2001.96,2844.58 C46.1@2050.01,2892.63 2039.98,2892.63 v1(2010.04,2922.57)
  Bottom Layer w10: v1(2010.04,2922.57) 2054.92,2877.69 2107.48,2877.69 2154.87,2830.3 2154.87,2258.88 TP47.1@2150.72,2254.73
3VDDM: C46.2 C49.2 R51.2 TP49.1 U6.13 | length 1088
  Top Layer w10: U6.13@1951.57,2791.18 2031.51,2791.18 2045.98,2805.65 2045.98,2833.47 C46.2@2050.01,2837.51 ; C46.2@2050.8,2838.29 2058.43,2845.92 2069.23,2845.92 2090.54,2867.23 2102.3,2867.23 2116,2880.93 C49.2@2116,2881.36 2258.22,2881.36 v1(2328.48,2811.1)
  Top Layer w35: v1(2328.48,2811.1) 2370.95,2811.1 R51.2@2372.36,2812.52
  Bottom Layer w10: v1(2328.48,2811.1) 2328.48,2323.26 TP49.1@2397.02,2254.73
3VDDP: D12.1 FB9.1 J28.3 | length 581.7
  Top Layer w20: 800.5,2725 800.5,2942.94 D12.1@840,2982.44
  Top Layer w35: J28.3@629.87,2625.72 729.15,2725 800.5,2725 FB9.1@896.69,2725
3VDDP_filtered: C42.1 C43.1 C44.2 FB15.2 J29.2 J30.1 R34.1 R35.1 R36.1 TP44.1 U6.4 | length 1008
  Top Layer w10: C44.2@1460,2807.38 1474.58,2792.8 U6.4@1579.06,2792.8
  Bottom Layer w35: J30.1@1153.48,3299.33 TP44.1@1498.48,3299.33 ; v1@1241.6,2796.58 1241.6,3211.63 J29.2@1328.48,3298.51
  other v1: 1240.83,2797.53
3VDRV: R46.1 R48.1 TP50.1 U6.16 | length 934.2
  Top Layer w10: U6.16@1960.95,2869.57 1960.95,2912.86 ; TP50.1@2000,3560 1960.95,3520.95 1960.95,2912.86 ; R46.1@2050.01,3001.92 1960.95,2912.86
  Top Layer w35: R46.1@2050.01,3001.92 2111.92,3001.92 R48.1@2140,3030
3VGATE: C54.2 C55.2 D11.2 Q5.1 R48.2
3VSSP: C45.2 C47.2 C52.2 FB10.1 J17.1 J24.2 R50.1 U8.4 U8.9 | length 1765.4
  Top Layer w35: J24.2@314.96,2007.92 185,2137.88 185,2884.73 277.5,2977.23 332.5,2977.23 414.3,3059.02 448.76,3059.02 449.96,3060.22 C45.2@449.96,3061.21 ; v1(855.67,2803.53) 894.55,2803.53 FB10.1@896.69,2805.67
  Bottom Layer w35: v2@564.88,3137.32 749.22,2952.99 749.22,2909.98 v1(855.67,2803.53)
  other v2: 565.12,3138.19 545.43,3162.8 584.8,3162.8 565.12,3187.4
3VSSP_filtered: C42.2 C43.2 C44.1 FB16.2 TP45.1 U6.3 U6.8 | length 1196.4
  Top Layer w10: C44.1@1460,2863.33 C44.1@1460,2865.58 ; C44.1@1460,2866.6 1472.71,2853.89 1488,2853.89 1522.48,2819.42 v1(1522.48,2818.39) U6.3@1579.06,2818.39 ; U6.8@1579.06,2690.43 1580,2689.49 v1(1580,2615.96)
  Top Layer w20: FB16.2@1120.08,2807.38 1163.14,2807.38 1275.92,2920.16 1308.5,2920.16 1320,2931.66 1386.94,2864.72 1455.86,2864.72 C44.1@1460,2860.58 ; TP45.1@1540,2300 1580,2340 v1(1580,2615.96)
  Bottom Layer w20: v1(1522.48,2818.39) 1580,2760.87 v1(1580,2615.96)
3VSSS: C48.1 C49.1 C50.1 C53.2 D14.2 J32.1 J32.2 R37.2 R45.1 R52.1 TP52.1 U6.9 U6.14 U9.2 U9.4 U9.5 | length 1111.8
  Top Layer w10: U6.9@1960.95,2690.43 2010.83,2640.55 R37.2@2030,2640.55 ; U6.14@1960.95,2818.39 1963.03,2820.47 v1(2015.36,2820.47) ; U9.2@2536.02,2745.45 2742.87,2745.45 2751.1,2737.22 R52.1@2751.1,2675.72
  Top Layer w20: R37.2@2030,2640.55 2060.08,2640.55 C50.1@2090,2670.47 ; v1(2130,2820) 2168.58,2820 C48.1@2170,2818.58 2171.89,2820.47 R45.1@2240.07,2820.47 ; C53.2@2371.34,2643.87 2417.34,2643.87 2467.64,2694.17 2467.64,2745.39 ; v1(2424.02,2812.52) 2424.02,2784.64 U9.4@2425.87,2782.8 U9.5@2425.87,2745.39 2467.64,2745.39 ; U9.2@2534.13,2745.39 2467.64,2745.39
  Top Layer w35: C49.1@2116,2944.36 2116.62,2943.74 v1(2159.43,2943.74)
  Bottom Layer w10: v1@2015.84,2820 v1(2130,2820)
  Bottom Layer w20: v1(2015.36,2820.47) v1@2015.84,2820
  other v1: 1985.89,2665.49
4ALM1_CMP: C10.2 R13.1 TP17.1 U1.11 | length 1338.9
  Top Layer w10: U1.11@1951.57,862.87 2083.26,862.87 C10.2@2090.62,855.51
  Top Layer w20: C10.2@2090,854.53 2090.98,855.51 v1(2134.98,855.51)
  Top Layer w35: v1(2295.06,1158.98) 2339.23,1158.98 R13.1@2340.28,1160.02
  Signal Layer 1 w20: TP17.1@2036.59,184.16 2163.87,311.45 2163.87,495.42 2134.98,524.31 v1(2134.98,855.51)
  Bottom Layer w20: v1(2134.98,855.51) 2198.68,919.2 2198.68,1062.59 v1(2295.06,1158.98)
4CE: J8.2 TP1.1 U1.2 | length 928
  Top Layer w10: TP1.1@1165,1687.75 1165,1520.54 1250,1435.54 1250,1285.7 1499.54,1036.16 1499.54,987.64 1523.2,963.98 U1.2@1579.06,963.98
4EN: J6.1 TP2.1 U1.1 | length 828.6
  Top Layer w10: TP2.1@1340,1689.72 1340,1519.72 1409.46,1450.26 1409.46,1309.07 1522.17,1196.36 1522.17,996.26 1528.86,989.57 U1.1@1579.06,989.57
4FLT1_CMP: C8.2 R14.1 TP11.1 U1.12 | length 1258.8
  Top Layer w10: U1.12@1951.57,888.46 C8.2@2159.55,888.46
  Top Layer w20: C8.2@2169.15,886.99 2163.4,892.73 2163.4,930.14 2167.79,934.54 v1(2167.79,935.62) 2262.17,1030 R14.1@2340.28,1030
  Signal Layer 1 w20: v1(2167.79,935.62) 2167.79,554.87 2191.74,530.92 2191.74,244.52 TP11.1@2252.1,184.16
4HV+: D6.1 D7.1 J13.1 J13.2
4LDO_IN+: C5.1 J5.1 U2.5 U2.8 | length 532
  Top Layer w10: C5.1@449.96,1244.2 450.62,1243.54 v1(485,1243.54) U2.8@509.76,1243.54 ; v1(485,1329.72) 487.62,1329.72 497.86,1319.49 507.16,1319.49 U2.5@508.26,1318.39
  Bottom Layer w20: v1(485,1329.72) 485,1176.29 629.87,1031.42 J5.1@629.87,945.72
4LDO_OUT: C14.1 C15.1 D5.2 R11.2 U2.1 | length 57.2
  Top Layer w20: D5.2@835,1152.34 C15.1@835,1208.5 C15.1@835.72,1207.78
4nALM1: R3.2 TP4.1 U1.7 | length 956.5
  Top Layer w10: R3.2@1430,654.72 1431.78,656.5 1464.14,656.5 1528.86,721.22 v1(1528.86,745.72) 1528.86,821.14 1540.67,832.95 1581.29,832.95 U1.7@1584.36,836.02
  Bottom Layer w10: TP4.1@1390,134.72 1390,464.72 1528.86,603.58 v1(1528.86,745.72)
4nFLT1: R2.2 TP7.1 U1.6 | length 1054.6
  Top Layer w10: R2.2@1430,744.72 1431.92,746.65 1464.14,746.65 1499.54,782.04 v1(1499.54,810.51) 1499.54,838.98 1522.17,861.61 U1.6@1584.36,861.61
  Bottom Layer w10: TP7.1@1155,134.72 1155,274.72 1486.17,605.9 1486.17,797.15 v1(1499.54,810.51)
4PGOOD: R1.2 TP3.1 U1.5 | length 1143.6
  Top Layer w10: R1.2@1430,834.72 1447.09,851.81 1464.14,851.81 v1(1481.84,869.51) 1499.54,887.2 U1.5@1584.36,887.2
  Bottom Layer w10: TP3.1@920,134.72 1464,678.72 1464,851.67 v1(1481.84,869.51)
4RESP: R4.1 U1.10 | length 88
  Top Layer w10: U1.10@1951.57,837.28 2009.05,837.28 R4.1@2030.62,815.71
4VDDH: C6.1 R15.2 TP9.1 U1.15 | length 899.2
  Top Layer w10: U1.15@1960.95,963.98 1964.02,967.05 1997.03,967.05 2033.48,1003.5 2038.01,1003.5 C6.1@2046.79,1012.28 ; TP9.1@2209.59,1550 2289.92,1469.67 2289.92,1320
  Top Layer w35: C6.1@2046.79,1012.28 2046.79,1076.88 2289.92,1320 R15.2@2411.58,1320
4VDDM: C6.2 C9.2 TP12.1 U1.13 | length 895.8
  Top Layer w10: U1.13@1960.95,912.8 2019.51,912.8 2041.51,934.8 2041.51,951.87 2051.84,962.21 2069.38,962.21 2093.03,985.85 2094.02,985.85 C9.2@2107.72,999.55
  Top Layer w35: C9.2@2107.72,999.55 2109.66,1001.5 v1(2150,1001.5)
  Bottom Layer w10: v1(2150,1001.5) 2173.79,1025.29 2173.79,1304.62 TP12.1@2419.17,1550
4VDDP: D5.1 FB1.1 J5.3 | length 577.1
  Top Layer w20: 775,850 787.5,862.5 787.5,949.81 835,997.31 D5.1@835,1097.22
  Top Layer w35: J5.3@629.87,745.72 734.15,850 775,850 787.5,850 FB1.1@891.69,850
4VDDP_filtered: C1.1 C2.1 C4.2 FB7.2 J6.2 J8.1 R1.1 R2.1 R3.1 TP5.1 U1.4 | length 1008
  Top Layer w10: C4.2@1460,927.37 1474.58,912.79 U1.4@1579.06,912.8
  Bottom Layer w35: J8.1@1166.17,1412.11 TP5.1@1511.17,1412.11 ; v1@1254.29,909.36 1254.29,1324.41 J6.2@1341.17,1411.29
  other v1: 1253.52,910.32
4VDRV: R7.1 R10.1 TP13.1 U1.16 | length 1245.6
  Top Layer w10: U1.16@1960.95,989.57 1964.02,992.64 v1(1964.02,1036.16) 2000,1072.14 TP13.1@2000,1550
  Top Layer w35: v1(2290.86,728.83) 2290.86,693.11 R7.1@2293.1,690.87 2349.13,690.87 2371,669 2377.5,669 2385,661.5 R10.1@2385,655
  Bottom Layer w35: v1(1964.02,1036.16) 1964.02,924.52 2070.4,818.14 2201.55,818.14 v1(2290.86,728.83)
4VGATE: C17.2 C18.2 D1.2 Q2.1 R10.2
4VSSP: C5.2 C7.2 C15.2 FB2.1 J2.1 J3.2 R12.1 U2.4 U2.9 | length 1593.2
  Top Layer w35: J3.2@309.86,294.49 185,419.36 185,1004.72 277.5,1097.22 332.5,1097.22 414.3,1179.02 448.76,1179.02 449.96,1180.22 C5.2@449.96,1181.21 ; v1(842.65,925.67) 886.76,925.67 FB2.1@888.46,927.37
  Bottom Layer w35: v2(563.38,1255.39) 563.38,1202.77 v1@841.56,924.58
  other v2: 543.69,1280 583.06,1280 563.38,1304.61
4VSSP_filtered: C1.2 C2.2 C4.1 FB8.2 TP6.1 U1.3 U1.8 | length 1250.4
  Top Layer w10: C4.1@1460,986.6 1460,983.3 1473.86,969.44 1479.02,969.44 1480.02,968.44 1492.43,968.44 v1(1522.48,938.39) U1.3@1579.06,938.39 ; U1.8@1579.06,810.43 1580,809.49 v1(1580,735.96)
  Top Layer w20: FB8.2@1120.08,927.37 1163.14,927.37 1275.92,1040.16 1308.5,1040.16 1320,1051.65 1386.94,984.72 1455.86,984.72 C4.1@1460,980.58 ; TP6.1@1540,365 1580,405 v1(1580,735.96)
  Bottom Layer w20: v1(1522.48,938.39) 1580,880.87 v1(1580,735.96)
4VSSS: C8.1 C9.1 C10.1 C18.1 D10.2 J9.1 J9.2 Q2.3 R4.2 R20.1 TP19.1 U1.9 U1.14 | length 87
  Top Layer w10: U1.14@1960.95,938.39 2009.92,938.39 v1(2010.04,938.5)
  Top Layer w35: C9.1@2107.72,1063.53 2109.19,1065 v1(2145,1065)
  other v1: 1964.02,755 2265.5,938.5
NetC7_1: C7.1 U2.6 | length 67.4
  Top Layer w10: C7.1@450.62,1316.42 474.24,1292.8 U2.6@508.26,1292.8
NetC11_2: C11.2 R8.1 R9.2 U3.2 | length 158.3
  Top Layer w6: U3.2@625,5044.41 676.34,5044.41 730,5044.41 771.97,5044.41 R8.1@780,5052.44
NetC13_1: C13.1 U3.6 | length 100.3
  Top Layer w10: C13.1@440,5124.14 440,5118.81 488.81,5070 U3.6@514.76,5070
NetC14_2: C14.2 R11.1 R12.2 U2.2 | length 158.9
  Top Layer w10: U2.2@618.49,1267.2 769.17,1267.2 R12.2@775,1261.38
NetC17_1: C17.1 D6.3 Q2.2
NetC30_2: C30.2 R32.1 R33.2 U5.2 | length 157.4
  Top Layer w10: U5.2@620,6914.41 673.06,6914.41 C30.2@676.34,6911.13 772.49,6911.13 R32.1@775,6908.62
NetC32_1: C32.1 U5.6 | length 65.2
  Top Layer w10: C32.1@449.96,6952.96 462.92,6940 U5.6@509.76,6940
NetC47_1: C47.1 U8.6 | length 90.9
  Top Layer w10: C47.1@445,3211.38 445,3192.64 462.92,3174.73 U8.6@509.76,3174.73
NetC51_2: C51.2 R49.1 R50.2 U8.2 | length 162.4
  Top Layer w6: U8.2@620.24,3150 773.62,3150 R49.1@780,3143.62
NetC53_1: C53.1 R51.1 U9.6 | length 115.5
  Top Layer w20: C53.1@2371.34,2697.07 2382.26,2707.99 U9.6@2425.87,2707.99
  Top Layer w35: C53.1@2371.34,2697.07 2372.36,2698.1 R51.1@2372.36,2753.07
NetD1_1: D1.1 R7.2 | length 89.9
  Top Layer w35: R7.2@2293.1,631.42 2293.1,557.4 D1.1@2304.36,546.14
NetD2_1: D2.1 R16.2 | length 96.6
  Top Layer w35: R16.2@2048.5,4189.02 2048.5,4110.53 D2.1@2061.28,4097.76
NetD3_1: D3.1 R30.2 | length 94.3
  Top Layer w35: R30.2@2043.84,4982.44 2043.84,5052.12 D3.1@2061.28,5069.55
NetD4_1: D4.1 R17.2 | length 109.3
  Top Layer w35: R17.2@2050.01,6825.71 2050.01,6919.05 D4.1@2061.28,6930.32
NetD6_2: D6.2 R15.1 R18.2 | length 69.5
  Top Layer w35: R15.1@2474.57,1320 2474.57,1254 R18.2@2477.12,1251.5
NetD7_2: D7.2 D10.1 | length 475
  Bottom Layer w35: D10.1@3415,795 D7.2@3415,1270
NetD11_1: D11.1 R46.2 | length 106.2
  Top Layer w35: R46.2@2050.01,3061.37 2050.01,3151.64 D11.1@2061.28,3162.91
NetD13_2: D13.2 D14.1 | length 480
  Bottom Layer w35: D14.1@3415,2570 D13.2@3415,3050
NetD15_1: D15.1 D16.2 | length 525
  Bottom Layer w35: D16.2@3415,4410 D15.1@3415,4935
NetD17_2: D17.2 D18.1 | length 511.4
  Bottom Layer w35: D18.1@3415,6300 D17.2@3415,6811.42
NetFB1_2: FB1.2 FB7.1 | length 58.4
  Top Layer w35: FB1.2@978.31,850 FB7.1@1036.69,850
NetFB2_2: FB2.2 FB8.1 | length 58.4
  Top Layer w35: FB2.2@978.31,926.56 FB8.1@1036.69,926.56
NetFB3_2: FB3.2 FB11.1 | length 53.4
  Top Layer w35: FB3.2@983.31,4621.56 FB11.1@1036.69,4621.56
NetFB4_2: FB4.2 FB12.1 | length 53.4
  Top Layer w35: FB4.2@983.31,4701.56 FB12.1@1036.69,4701.56
NetFB5_2: FB5.2 FB13.1 | length 53.4
  Top Layer w35: FB5.2@983.31,6495 FB13.1@1036.69,6495
NetFB6_2: FB6.2 FB14.1 | length 53.8
  Top Layer w35: FB6.2@983.31,6573.22 FB14.1@1037.15,6573.22
NetFB9_2: FB9.2 FB15.1 | length 53.4
  Top Layer w35: FB9.2@983.31,2725 FB15.1@1036.69,2725
NetFB10_2: FB10.2 FB16.1 | length 55.4
  Top Layer w35: FB10.2@983.31,2803.53 FB16.1@1038.66,2803.53
NetJ1_1: J1.1 J3.1 J5.2 | length 1279.9
  Top Layer w20: J1.1@185,1490.55 200,1490.55 300,1390.55
  Top Layer w30: v3(300,1362.74) 300,1390.55
  Bottom Layer w35: v3(300,1362.74) 300,1175.59 J5.2@629.87,845.72 ; J3.1@314.96,533.19 J5.2@627.49,845.72
NetJ4_1: J4.1 J7.2 J11.1 | length 1436.1
  Top Layer w20: J4.1@189.94,5264.88 204.94,5264.88 304.94,5164.88
  Top Layer w30: v3(304.94,5137.07) 304.94,5164.88
  Bottom Layer w35: v3(304.94,5137.07) 304.94,4949.92 634.81,4620.05 319.9,4305.14 J11.1@319.9,4152.25
NetJ15_1: J15.1 J24.1 J28.2 | length 1436.1
  Top Layer w20: J15.1@185,3370.55 200,3370.55 300,3270.55
  Top Layer w30: v3(300,3242.74) 300,3270.55
  Bottom Layer w35: v3(300,3242.74) 300,3055.59 J28.2@629.87,2725.72 314.96,2410.81 J24.1@314.96,2257.92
